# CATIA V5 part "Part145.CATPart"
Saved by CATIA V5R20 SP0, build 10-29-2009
Part number: FA 105700-3
Revision: ANY
Definition: UNKNOWN
Nomenclature: FA 105700-3
Source: Unknown
Bounding box of the stored display mesh (mm): x -2.687 to 2.687, y -2.475 to 2.475, z -2.5 to 2.5
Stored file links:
  C:\Users\Utente\Desktop\IO LAVORO\3D X SITO CF\CUMSA\3D files FA\FA 105700\Part145.CATPart

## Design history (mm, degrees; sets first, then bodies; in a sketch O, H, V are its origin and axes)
Body1 "Chaflán4" (main body)
  Solid1: solid without history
